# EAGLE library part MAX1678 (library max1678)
MAX1678 The MAX1678 is a high-efficiency, low-voltage, synchronous- rectified, step-up DC-DC converter intended for use in devices powered by 1 to 3-cell alkaline, NiMH, or NiCd batteries or a 1-cell lithium battery. It guarantees a 0.87V start-up voltage and features a low 37µA quiescent supply current.
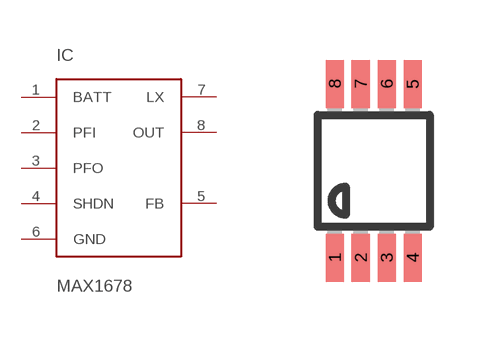
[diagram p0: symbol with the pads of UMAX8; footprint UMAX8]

Designator prefix IC

## MAX1678  [UMAX8]
1  BATT  pwr
2  PFI  in
3  PFO  out
4  SHDN  in
5  FB
6  GND  pwr
7  LX
8  OUT  out

## Footprint UMAX8 (pad centres in mm)
micro MAX Package
smd 0.45 x 1.2: 1 -0.975,-2.175; 2 -0.325,-2.175; 3 0.325,-2.175; 4 0.975,-2.175; 5 0.975,2.175; 6 0.325,2.175; 7 -0.325,2.175; 8 -0.975,2.175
